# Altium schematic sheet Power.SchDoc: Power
size A4; Date: Not used; ApprovedBy: Not used; CheckedBy: Not used; Author: Not used; CompanyName: STMicroelectronics; DrawnBy: Not used; Engineer: Not used; Organization: Not used; Address1: Not used; Address2: Not used; Address3: Not used; Address4: Not used; DocumentNumber: Not used; Revision: Not used; SheetNumber: 9; SheetTotal: 12
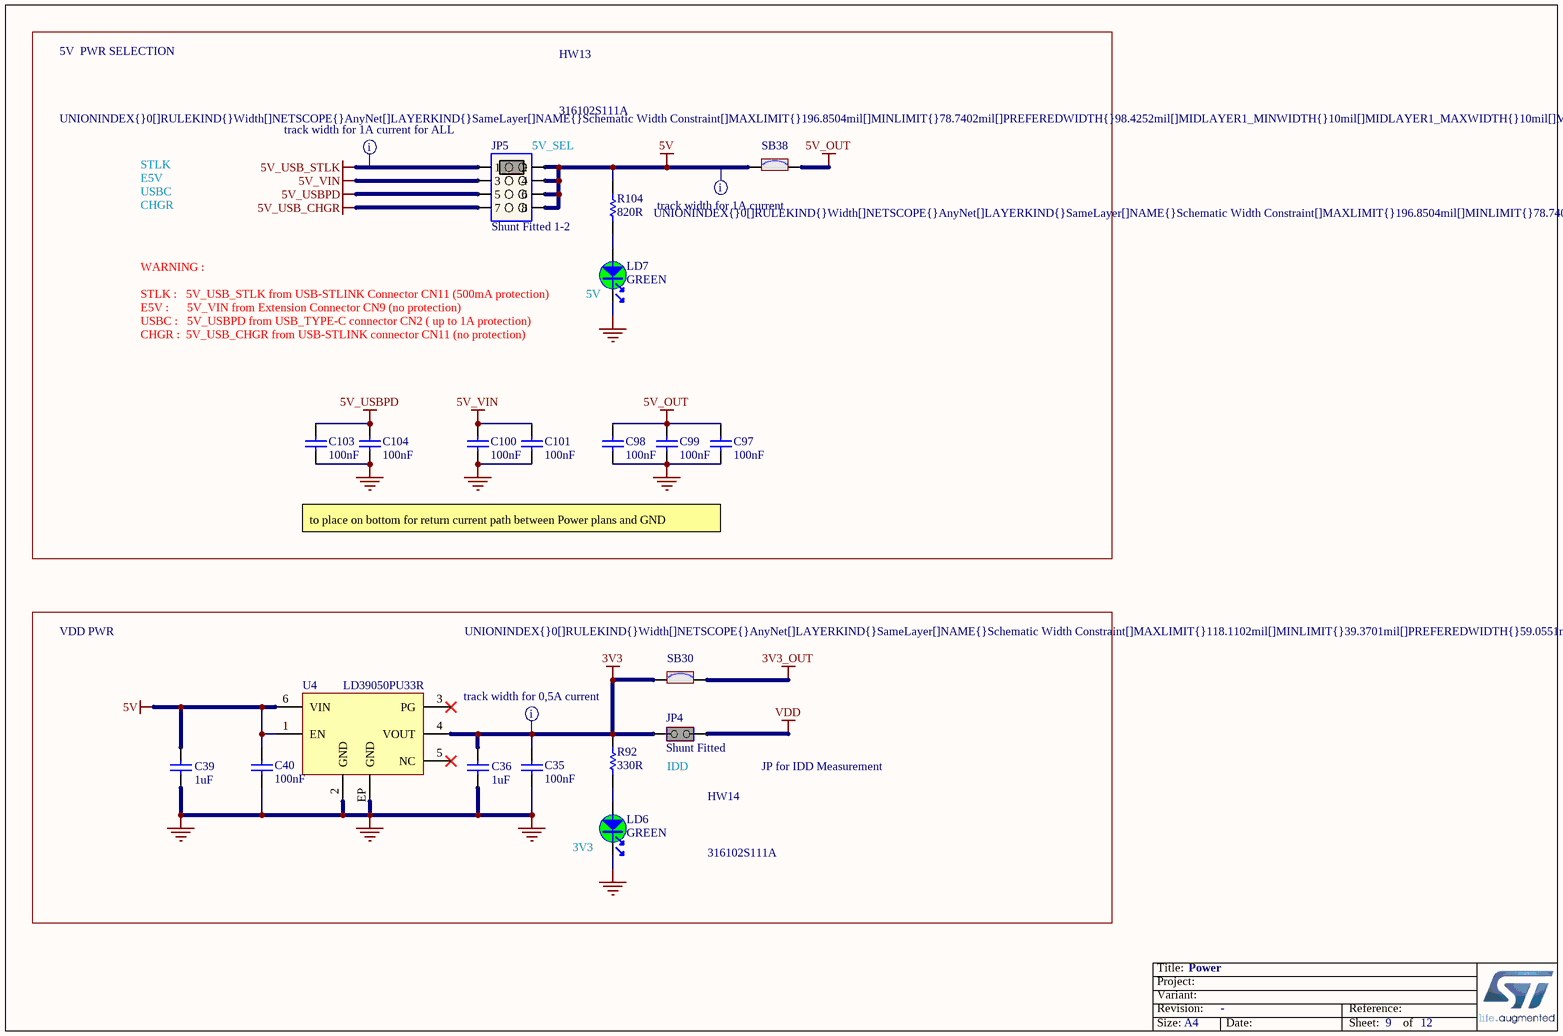
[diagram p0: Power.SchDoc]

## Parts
C35  value 100nF  [C0402]
C36  value 1uF  [C0603]
C39  value 1uF  [C0603]
C40  value 100nF  [C0402]
C97  value 100nF  [C0402]
C98  value 100nF  [C0402]
C99  value 100nF  [C0402]
C100  value 100nF  [C0402]
C101  value 100nF  [C0402]
C103  value 100nF  [C0402]
C104  value 100nF  [C0402]
HW13  value 316102S111A  (hidden comment: JUMPER_OPEN)
HW14  value 316102S111A  (hidden comment: JUMPER_OPEN)
JP4  value Shunt Fitted  [CON_988-JIUBABA_313102S111116]  (hidden comment: Jumper_Header 2x1 Fitted)
JP5  value Shunt Fitted 1-2  [CON_988-JIUBABA_313208S141116]  (hidden comment: Jumper_Header 4x2 Fitted 1-2)
LD6  value GREEN  [LED_0603_GREEN]
LD7  value GREEN  [LED_0603_GREEN]
R92  value 330R  [R0603]
R104  value 820R  [R0603]
SB30  (no value)  [SOLDER-BRIDGE_R0603-0R]
SB38  (no value)  [SOLDER-BRIDGE_R0603-0R]
U4  value LD39050PU33R  [ICC_DFN6-EPAD_3X3_P095]

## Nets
3V3: C35.2 C36.2 JP4.1(COMMON) R92.2 SB30.1 U4.4(VOUT)
3V3_OUT: SB30.2
5V: C39.2 C40.2 JP5.2 JP5.4 JP5.6 JP5.8 R104.2 SB38.1 U4.1(EN) U4.6(VIN)
5V_OUT: C97.2 C98.2 C99.2 SB38.2
5V_USB_CHGR: JP5.7
5V_USB_STLK: JP5.1
5V_USBPD: C103.2 C104.2 JP5.5
5V_VIN: C100.2 C101.2 JP5.3
GND: C35.1 C36.1 C39.1 C40.1 C97.1 C98.1 C99.1 C100.1 C101.1 C103.1 C104.1 LD6.2 LD7.2 U4.2(GND) U4.EP(GND)
VDD: JP4.2(NO)
NetLD6_1: LD6.1 R92.1
NetLD7_1: LD7.1 R104.1

Not connected (* = marked no-connect by the designer): U4 3(PG)* 5(NC)*

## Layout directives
rule Width Constraint [Pref Width = 2.5mm    Min Width = 2mm    Max Width = 5mm]: 5V, 5V_USB_STLK
rule Width Constraint [Pref Width = 1.5mm    Min Width = 1mm    Max Width = 3mm]: 3V3

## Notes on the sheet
- 5V  PWR SELECTION
- STLK
- E5V
- (near JP5) 5V_SEL
- USBC
- CHGR
- (near LD7) STLK :   5V_USB_STLK from USB-STLINK Connector CN11 (500mA protection)
- E5V :      5V_VIN from Extension Connector CN9 (no protection)
- WARNING :
- (near LD7) 5V
- USBC :   5V_USBPD from USB_TYPE-C connector CN2 ( up to 1A protection)
- CHGR :  5V_USB_CHGR from USB-STLINK connector CN11 (no protection)
- to place on bottom for return current path between Power plans and GND
- VDD PWR
- IDD
- JP for IDD Measurement
- (near LD6) 3V3

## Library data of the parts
C35 C40 C97-C101 C103 C104 = MCD-00102: Capacitor, MLCC, 100nF, 16V, X7R, 10%, 0402, T=0,5mm; Manufacturer_Part_Number: CC0402KRX7R7BB104; Manufacturer: YAGEO; Alternate_Manufacturer_Part_Number: GCM155R71C104KA55D; Alternate_Manufacturer: MURATA; Provided_By: SUBCO
C36 C39 = MCD-00010: Capacitor, MLCC, 1uF, 16V, X5R, 10%, 0603, T=0,8mm; Manufacturer_Part_Number: CC0603KRX5R7BB105; Manufacturer: YAGEO; Provided_By: SUBCO
HW13 HW14 = MCD-01849: Jumper, height 6mm, Black, 2.54mm, 3A, 20 mohm, open; Part_Type: Mechanical; Manufacturer: JIUBABA; Provided_By: SUBCO
JP4 = MCD-01662: Header 2x1, 2.54mm, VR, TH, height 6 mm / 3 mm, total 11.6mm - Shunt Fitted by default; Part_Type: Connector; Manufacturer_Part_Number: 313102S111116; Manufacturer: JIUBABA; Provided_By: SUBCO
JP5 = MCD-01661: Header, 4x2, 2,54mm, VR, TH, Height 6mm/3m, total 11.6mm - Shunt Fitted 1-2; Part_Type: Connector; Manufacturer_Part_Number: 313208S141116; Manufacturer: JIUBABA; Provided_By: SUBCO
LD6 LD7 = MCD-00050: LED, Green, 0603; Manufacturer_Part_Number: 19-213SYGC/S530-E2/TR8; Manufacturer: EVERLIGHT; Part_Type: Display; Provided_By: SUBCO
R92 = MCD-00197: Resistor,330R,0603,1%,1/10W; Manufacturer_Part_Number: RC0603FR-07330RL; Manufacturer: YAGEO; BMS_Part_Number: 9129729; Provided_By: SUBCO
R104 = MCD-00528: Resistor,820R,0603,1%,1/10W; Manufacturer_Part_Number: RC0603FR-07820RL; Manufacturer: YAGEO; BMS_Part_Number: 9129759; Provided_By: SUBCO
SB30 SB38 = MCD-00071: Solder Bridge ON; Part_Type: Mechanical; Manufacturer_Part_Number: RC0603JR-070RL; Manufacturer: YAGEO; Provided_By: SUBCO
U4 = MCD-00215: Low quiescent current and low noise voltage regulators; Manufacturer: STMICROELECTRONICS; Part_Type: IC; BMS_Part_Number: 9176126; Provided_By: SUBCO with ST control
